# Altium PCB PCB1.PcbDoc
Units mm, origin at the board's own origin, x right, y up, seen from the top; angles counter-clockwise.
Board outline 64.13 x 24.77 mm, 2 copper layers (Top Layer, Bottom Layer); 36 components, 34 nets, 189 pads, 64 vias.
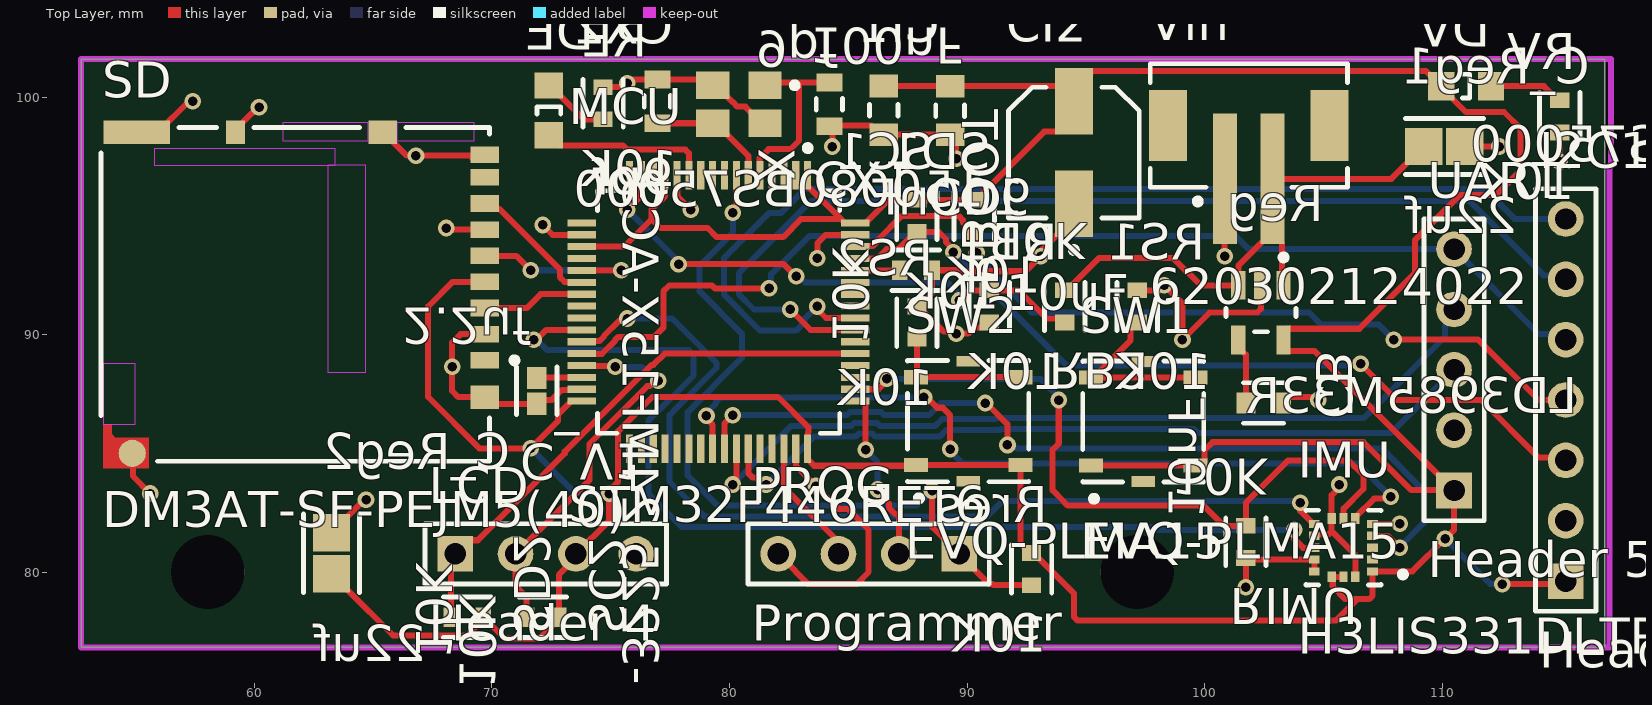
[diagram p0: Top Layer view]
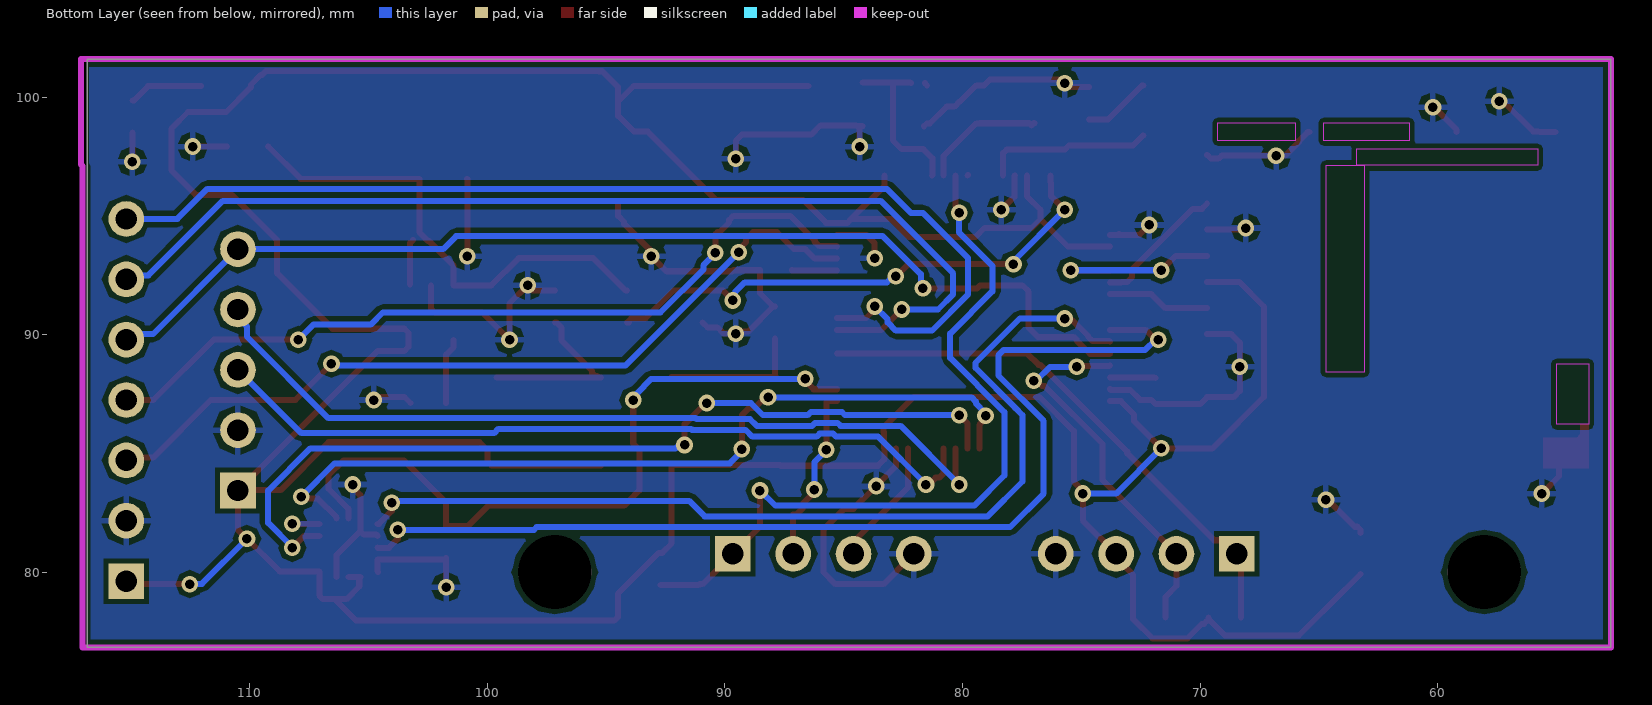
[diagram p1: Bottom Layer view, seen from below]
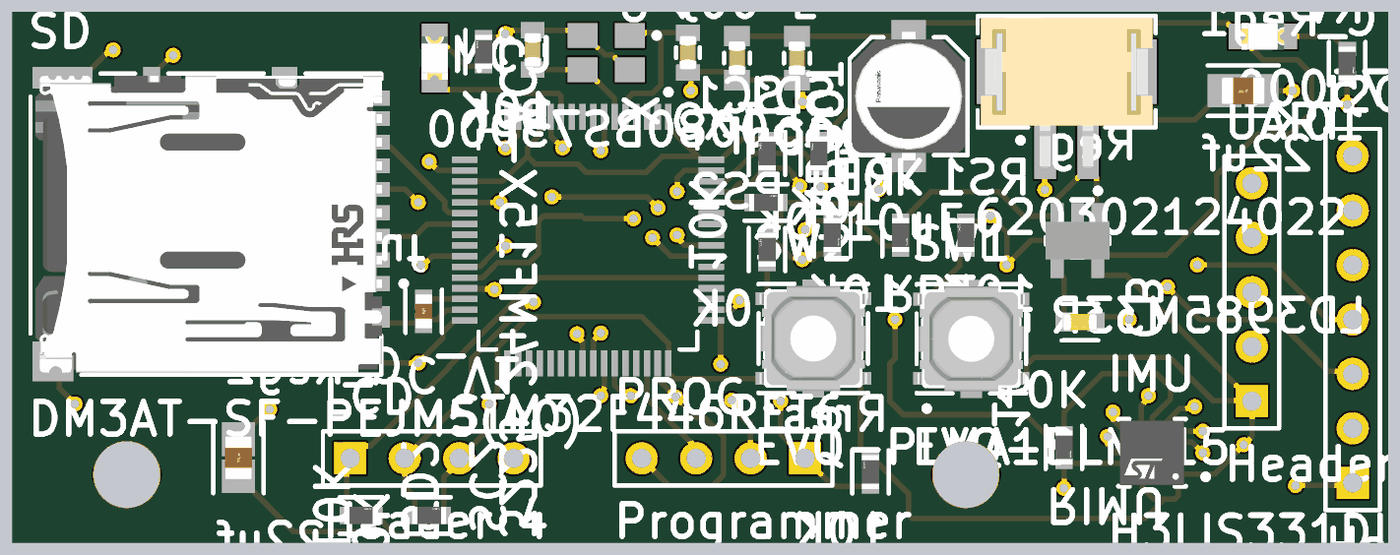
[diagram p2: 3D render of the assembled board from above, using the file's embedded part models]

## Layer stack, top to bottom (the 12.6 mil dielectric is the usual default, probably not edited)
Top Solder: solder mask 0.0102, Solder Resist, Dk 3.5
Top Layer: signal copper 0.0356
Dielectric 1: dielectric 0.32, FR-4, Dk 4.8
Bottom Layer: signal copper 0.0356
Bottom Solder: solder mask 0.0102, Solder Resist, Dk 3.5

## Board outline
52.705,76.835 52.705,101.6 116.84,101.6 116.84,76.835

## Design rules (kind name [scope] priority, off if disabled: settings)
Clearance [All] p1: gap=0.2 ignorepadtopadclearanceinfootprint=FALSE except(0.127: Arc-Arc Arc-Track Track-Track SMDPad-SMDPad)
PolygonConnect [All] p1: connectstyle=Relief reliefconductorwidth=0.254 reliefentries=4 polygonreliefangle="90 Angle" airgapwidth=0.254
RoutingVias [All] p1: holewidth=0.711 width=1.27 viastyle="Through Hole" minholewidth=0.711 minwidth=1.27 maxholewidth=0.711 maxwidth=1.27
SolderMaskExpansion [All] p1: expansion=0.102 istentingtop=FALSE
Width [All] p1: maxlimit=0.5 minlimit=0.254 preferedwidth=0.254
30 further rules are at their usual default settings.

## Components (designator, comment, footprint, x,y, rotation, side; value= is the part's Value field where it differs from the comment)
C_Reg1 "22uf" FP-C2012-125-0_2-IPC_A 110.084,97.917 r180 top
C_Reg2 "22uf" FP-C2012-125-0_2-IPC_A 63.246,80.797 r270 top
C_V1 "2.2uf" FP-C1608-080-0_1-IPC_C 71.882,87.63 r270 top
CB "10nF" FP-CC0603-DA-MFG 102.477,87.122 r0 top value="10 nF"
CD6 "100nF" FP-CGA3E-0_3-0_1-IPC_A 89.281,99.432 r270 top
CI1 "100nF" FP-CGA3E-0_3-0_1-IPC_A 86.487,99.441 r90 top
CI2 "10uF" FP-SC-MFG 94.488,97.663 r90 top
CX1 "9pf" FP-CGA3E-0_3-0_1-IPC_B 84.201,99.695 r270 top
CX2 "9pf" FP-CGA3E-0_3-0_1-IPC_B 76.962,99.822 r90 top
DE "150080BS75000" 0805_A 72.39,99.441 r270 top
DV "150080BS75000" 0805_A 110.998,100.457 r180 top
I2C1 "Header 7" HDR1X7 115.189,79.629 r90 top
IMU "H3LIS331DLTR" FP-TFLGA16-7983231-MFG 105.836,81.034 r180 top
LCD "Header 4" HDR1X4 68.453,80.772 r0 top
MCU "STM32F446RET6" FP-LQFP64-5W-MFG 79.537,90.952 r270 top
PROG "Programmer" HDR1X4 89.662,80.772 r180 top
RB1 "10K" FP-RC0603-0_55-IPC_C 90.932,91.186 r270 top
RB2 "10K" FP-RC0603-0_55-IPC_C 94.107,91.186 r270 top
RBOOT "10K" FP-RC0603-0_55-IPC_C 87.842,92.71 r0 top
RE "10K" FP-RC0603-0_55-IPC_C 74.676,99.737 r90 top
Reg "LD3985M33R" FP-SOT23-5L-7049676-MFG 102.362,90.925 r270 top
RIMU "10K" FP-RC0603-0_55-IPC_C 101.727,81.28 r270 top
Rres "10K" FP-RC0603-0_55-IPC_C 92.71,80.137 r90 top
RS1 "10K" FP-RC0603-0_55-IPC_C 97.155,91.186 r90 top
RS2 "10K" FP-RC0603-0_55-IPC_C 87.884,90.509 r90 top
RV "10K" FP-RC0603-0_55-IPC_C 114.935,99.187 r270 top
SC1 "10K" FP-RC0603-0_55-IPC_C 87.884,94.996 r90 top
SC2 "10K" FP-RC0603-0_55-IPC_C 72.136,78.105 r0 top
SD "DM3AT-SF-PEJM5(40)" FP-DM3AT-SF-PEJM5_40-MFG 61.722,91.694 r270 top
SD1 "10K" FP-RC0603-0_55-IPC_C 90.297,94.996 r90 top
SD2 "10K" FP-RC0603-0_55-IPC_C 68.961,78.105 r0 top
SW1 "EVQ-PLMA15" FP-EVQ-PLMA15-MFG 97.409,86.345 r90 top
SW2 "EVQ-PLMA15" FP-EVQ-PLMA15-MFG 90.043,86.36 r90 top
UART "Header 5" HDR1X5 110.49,83.439 r90 top
Vin "620302124022" 620302124022 101.854,98.806 r180 top
X "TSX-3225 24MF15X-AC3" EPSON-TSX-3225_V 80.391,99.695 r180 top

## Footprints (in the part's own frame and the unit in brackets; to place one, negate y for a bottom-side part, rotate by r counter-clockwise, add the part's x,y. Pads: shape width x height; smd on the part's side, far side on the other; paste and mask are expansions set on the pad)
0805_A [mm] "Chip LED, 2-Leads, Body 2.0x1.3mm, IPC Medium Density"
  rect 1.1x1.2 smd: 1(-1.05,0) 2(1.05,0)
  silkscreen extent -0.15,-0.5 0.15,0.5, body extent -1,-0.63 1,0.63, height 0.68
620302124022 [mm] "2.00mm SMT Male Vertical Shrouded Header, 2p"
  rect 1x5.5 smd: 1(1,2.25) 2(-1,2.25)
  rect 1.6x3 smd: MP1(-3.4,0) MP2(3.4,0)
  silkscreen extent -4.15,-2.6 4.15,3.32, body extent -4,-2.5 4,4.51, height 6.77
EPSON-TSX-3225_V [mm] "SMD, 4-Leads, Body 3.2x2.5mm"
  rect 1.4x1.15 smd: 1(-1.1,-0.8) 2(1.1,-0.8) 3(1.1,0.8) 4(-1.1,0.8)
  silkscreen extent -2.48,-0.92 -2.23,-0.68, body extent -1.6,-1.25 1.6,1.25, height 0.6
FP-C1608-080-0_1-IPC_C [mm]
  rect 0.931x0.812 smd paste+0 mask+0: 1(-0.541,0) 2(0.541,0)
  silkscreen extent -1.01,-0.85 1.01,0.85, body extent -0.8,-0.4 0.8,0.4, height 0.9
FP-C2012-125-0_2-IPC_A [mm]
  rect 1.578x1.556 smd paste+0 mask+0: 1(-0.864,0) 2(0.864,0)
  silkscreen extent -1.65,-1.18 1.65,1.18, body extent -1,-0.63 1,0.63, height 1.45
FP-CC0603-DA-MFG [mm]
  rect 0.8x0.9 smd paste+0 mask+0: 1(-0.75,0) 2(0.75,0)
  silkscreen extent -0.85,-0.85 0.85,0.85, body extent -0.8,-0.4 0.8,0.4, height 0.9
FP-CGA3E-0_3-0_1-IPC_A [mm]
  rect 0.956x1.206 smd paste+0 mask+0: 1(-1.025,0) 2(1.025,0)
  silkscreen extent -0.25,-0.6 0.25,0.6, body extent -0.8,-0.4 0.8,0.4, height 1.1
FP-CGA3E-0_3-0_1-IPC_B [mm]
  rect 0.756x1.106 smd paste+0 mask+0: 1(-0.925,0) 2(0.925,0)
  silkscreen extent -0.25,-0.55 0.25,0.55, body extent -0.8,-0.4 0.8,0.4, height 1.1
FP-DM3AT-SF-PEJM5_40-MFG [mm]
  rect 0.7x1.2 smd paste+0 mask+0: 1(2.775,7.975) 2(1.675,7.975) 3(0.575,7.975) 4(-0.525,7.975) 5(-1.625,7.975) 6(-2.725,7.975) 7(-3.825,7.975) 8(-4.925,7.975) 9(-5.875,7.975)
  rect 1x0.8 smd paste+0 mask+0: 10(-6.825,-2.525)
  rect 1x1.2 smd paste+0 mask+0: 11(4.325,7.975) 12(-6.825,3.675)
  rect 1x2.8 smd paste+0 mask+0: 13(-6.825,-6.675)
  round 1.145 smd paste+0 mask+0: 14(6.689,-6.861)
  Top Layer region: 6.025,-6.175 7.325,-6.175 7.325,-8.075 5.475,-8.075 5.475,-7.725 5.875,-7.725 6.025,-7.575 6.025,-6.175
  Keep-Out Layer region: 2.925,-8.075 5.475,-8.075 5.475,-6.725 2.925,-6.725
  Keep-Out Layer region: -5.425,1.375 3.275,1.375 3.275,2.975 -5.425,2.975
  Keep-Out Layer region: -6.125,-5.925 -5.425,-5.925 -5.425,1.675 -6.125,1.675
  Keep-Out Layer region: -7.225,-0.525 -6.475,-0.525 -6.475,3.075 -7.225,3.075
  Keep-Out Layer region: -7.225,4.275 -6.475,4.275 -6.475,7.525 -7.225,7.525
  silkscreen extent -7.02,-8.17 7.02,9.35, body extent -6.93,-7.95 6.92,8.2, height 1.68
FP-EVQ-PLMA15-MFG [mm]
  rect 0.45x1 smd paste+0 mask+0: 1(-2.525,0) 2(2.525,0)
  rect 0.6x1 smd paste+0 mask+0: A(-1.85,2.2) A'(-1.85,-2.2) B(1.85,2.2) B'(1.85,-2.2)
  silkscreen extent -3.37,-2.55 2.55,2.55, body extent -2.85,-2.8 2.85,2.8, height 0.25
FP-LQFP64-5W-MFG [mm]
  rect 1.2x0.3 smd paste+0 mask+0: 1(-5.75,3.75) 2(-5.75,3.25) 3(-5.75,2.75) 4(-5.75,2.25) 5(-5.75,1.75) 6(-5.75,1.25) 7(-5.75,0.75) 8(-5.75,0.25) 9(-5.75,-0.25) 10(-5.75,-0.75) 11(-5.75,-1.25) 12(-5.75,-1.75) 13(-5.75,-2.25) 14(-5.75,-2.75) 15(-5.75,-3.25) 16(-5.75,-3.75) 33(5.75,-3.75) 34(5.75,-3.25) 35(5.75,-2.75) 36(5.75,-2.25) 37(5.75,-1.75) 38(5.75,-1.25) 39(5.75,-0.75) 40(5.75,-0.25) 41(5.75,0.25) 42(5.75,0.75) 43(5.75,1.25) 44(5.75,1.75) 45(5.75,2.25) 46(5.75,2.75) 47(5.75,3.25) 48(5.75,3.75)
  rect 0.3x1.2 smd paste+0 mask+0: 17(-3.75,-5.75) 18(-3.25,-5.75) 19(-2.75,-5.75) 20(-2.25,-5.75) 21(-1.75,-5.75) 22(-1.25,-5.75) 23(-0.75,-5.75) 24(-0.25,-5.75) 25(0.25,-5.75) 26(0.75,-5.75) 27(1.25,-5.75) 28(1.75,-5.75) 29(2.25,-5.75) 30(2.75,-5.75) 31(3.25,-5.75) 32(3.75,-5.75) 49(3.75,5.75) 50(3.25,5.75) 51(2.75,5.75) 52(2.25,5.75) 53(1.75,5.75) 54(1.25,5.75) 55(0.75,5.75) 56(0.25,5.75) 57(-0.25,5.75) 58(-0.75,5.75) 59(-1.25,5.75) 60(-1.75,5.75) 61(-2.25,5.75) 62(-2.75,5.75) 63(-3.25,5.75) 64(-3.75,5.75)
  silkscreen extent -7.02,-5.1 5.1,5.1
FP-RC0603-0_55-IPC_C [mm]
  rect 0.659x0.812 smd paste+0 mask+0: 1(-0.677,0) 2(0.677,0)
  silkscreen extent -1.01,-0.85 1.01,0.85, body extent -0.8,-0.4 0.8,0.4, height 0.55
FP-SC-MFG [mm]
  rect 2.8x1.6 smd paste+0 mask+0: 1(-2.15,0) 2(2.15,0)
  silkscreen extent -4.22,-2.75 2.75,2.75, body extent -3.8,-3 3.8,3, height 0.25
FP-SOT23-5L-7049676-MFG [mm]
  rect 1.2x0.6 smd paste+0 mask+0: 1(-1.15,0.95) 2(-1.15,0) 3(-1.15,-0.95) 4(1.15,-0.95) 5(1.15,0.95)
  silkscreen extent -2.45,-1.47 0.8,1.47, body extent -0.87,-1.5 0.88,1.5, height 1.45
FP-TFLGA16-7983231-MFG [mm]
  rect 0.45x0.35 smd paste+0 mask+0: 1(-1.225,1) 2(-1.225,0.5) 3(-1.225,0) 4(-1.225,-0.5) 5(-1.225,-1) 9(1.225,-1) 10(1.225,-0.5) 11(1.225,0) 12(1.225,0.5) 13(1.225,1)
  rect 0.35x0.45 smd paste+0 mask+0: 6(-0.5,-1.225) 7(0,-1.225) 8(0.5,-1.225) 14(0.5,1.225) 15(0,1.225) 16(-0.5,1.225)
  silkscreen extent -2.63,-1.57 1.57,1.57, body extent -1.5,-1.5 1.5,1.5, height 1
HDR1X4 [mm] "Connector; Header; 4 Position"
  rect 1.5x1.5 hole 0.9: 1(0,0)
  round 1.5 hole 0.9: 2(2.54,0) 3(5.08,0) 4(7.62,0)
  silkscreen extent -1.27,-1.27 8.89,1.27
HDR1X5 [mm] "Connector; Header; 5 Position"
  rect 1.5x1.5 hole 0.9: 1(0,0)
  round 1.5 hole 0.9: 2(2.54,0) 3(5.08,0) 4(7.62,0) 5(10.16,0)
  silkscreen extent -1.27,-1.27 11.43,1.27
HDR1X7 [mm] "Connector; Header; 7 Position"
  rect 1.5x1.5 hole 0.9: 1(0,0)
  round 1.5 hole 0.9: 2(2.54,0) 3(5.08,0) 4(7.62,0) 5(10.16,0) 6(12.7,0) 7(15.24,0)
  silkscreen extent -1.27,-1.27 16.51,1.27

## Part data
C_Reg1 C_Reg2: library part CMP-08246-007072-1, "Multilayer Ceramic Capacitors 22μF ±20% 16V X6S SMD 0805", Capacitance=22uF, Case Code (Imperial)=0805, Case Code (Metric)=2012, Dielectric=X6S, Dielectric Material=Ceramic, Max Operating Temperature=105°C, Min Operating Temperature=-55°C, Package Quantity=2000, Tolerance=20%, Voltage Rating=16V
C_V1: library part CMP-2000-04981-2, "Multilayer Ceramic Capacitors 4.7μF ±10% 16V X5R SMD 0603", Capacitance=4.7uF, Case Code (Imperial)=0603, Case Code (Metric)=1608, Dielectric=X5R, Dielectric Material=Ceramic, Max Operating Temperature=85°C, Min Operating Temperature=-55°C, Package Quantity=1, Tolerance=10%, Voltage=16V
CB: library part CMP-2100-03600-2, "CAP CER 10000PF 50V X7R 0603", Capacitance="10 nF", Manufacturer=YAGEO, Manufacturer Part Number=CC0603KRX7R9BB103, Package=CC0603-DA, Temperature="-55°C to +125°C", Temperature Characteristic=X7R, Temperature Coefficient=15%, Temperature Range High=+125°C, Temperature Range Low=-55°C, Tolerance=0.1, Voltage="50 V"
CD6 CI1: library part CMP-2000-07546-2, "Cap Ceramic 100nF 50V X7R 10% Pad SMD 0603 +125°C Automotive T/R", Case Code (Imperial)=0603, Case Code (Metric)=1608, Dielectric=X7R, Max Operating Temperature=125°C, Min Operating Temperature=-55°C, Package Quantity=1, Ratings=AEC-Q200, Tolerance=10%, Voltage=50V
CI2: library part CMP-05427-000087-1, "CAP ALUM 10UF 20% 35V SMD", Case/Package=Radial, Leakage Current=3uA, Max Operating Temperature=85°C, Min Operating Temperature=-40°C, Package Quantity=1, Ripple Current=30mA, Tolerance=20%, Voltage=35V
CX1 CX2: library part CMP-08246-000963-1, "Cap Ceramic 9pF 50V C0G 0.5pF Pad SMD 0603 +125°C Automotive T/R", Capacitance=9pF, Case Code (Imperial)=0603, Case Code (Metric)=1608, Dielectric=C0G, Max Operating Temperature=125°C, Min Operating Temperature=-55°C, Package Quantity=4000, Ratings=AEC-Q200, Voltage Rating=50V
DE DV: library part CMP-1426-00008-1, "SMD mono-color Chip LED, WL-SMCW, Blue", Color=Blue, Manufacturer="Wuerth Elektronik"
I2C1: "Header, 7-Pin"
IMU: library part CMP-12175-000002-1, "ACCEL 100-400G I2C/SPI 16TFLGA", Manufacturer=STMicroelectronics, Max Supply Voltage=3.6V, Min Supply Voltage=2.16V, Operating Supply Current=10-300uA, Package=TFLGA16-7983231, Temperature="-40°C to +85°C", Temperature Range High=+85°C, Temperature Range Low=-40°C
LCD: "Header, 4-Pin"
MCU: library part CMP-12105-000007-1, "IC MCU 32BIT 512KB FLASH 64LQFP", Ambient Temperature Range High=+85°C, Ambient Temperature Range Low=-40°C, Frequency=180MHz, Manufacturer=ST, Max Junction Temp=+105°C, Max Supply Voltage=3.6V, Min Supply Voltage=1.7V, Package=LQFP64-5W, Temperature="-40°C to +105°C"
PROG: library part "Header 4", "Header, 4-Pin"
RB1 RB2 RBOOT RE RIMU Rres RS1 RS2 RV SC1 SC2 SD1 SD2: library part CMP-2100-03664-2, "RES 10K OHM 1% 1/10W 0603", Case Code (Imperial)=0603, Case Code (Metric)=1608, Max Operating Temperature=155°C, Max Power Dissipation=100mW, Min Operating Temperature=-55°C, Resistance=10kR, Resistance Tolerance=1%, Resistor Type="Thick Film", Temperature Coefficient=100ppm/°C, Voltage Rating=75V, Voltage Rating (DC)=50V
Reg: library part CMP-0244-00328-2, "IC REG LINEAR 3.3V 150MA SOT23-5", Case/Package=SOT-23, Dropout Voltage=60mV, Input Bias Current=85uA, Max Input Voltage=6V, Max Operating Temperature=125°C, Max Output Current=150mA, Min Current Limit=300mA, Min Input Voltage=2.5V, Min Operating Temperature=-40°C, Min Output Voltage=3.3V, Output Voltage Accuracy=2%, Package Quantity=1, Quiescent Current=150uA
SD: library part CMP-11597-000006-1, "CONN MICRO SD R/A PUSH-PUSH SMD", Color=Black, Contact Resistance=100mR, Current Rating=500mA, Flammability Rating="UL94 V-0", Insulation Resistance=1GR, Max Operating Temperature=85°C, Max Voltage Rating (AC)=125V, Min Operating Temperature=-25°C, Package Quantity=400
SW1 SW2: library part CMP-05618-000006-1, "SWITCH TACTILE SPST-NO 0.02A 15V", Contact Current Rating=20mA, Contact Resistance=50mΩ, Manufacturer="Panasonic Electronic Components", Operating Force=2.6N, Package=0, Temperature="-20°C to +70°C", Temperature Range High=+70°C, Temperature Range Low=-20°C, Voltage Rating Dc=15V
UART: "Header, 5-Pin"
Vin: library part CMP-1502-00660-1, "Male Shrouded Header WR-WTB, SMT, Vertical, pitch 2 mm, 1 x 2 position", Contact Resistance=20mOhm, Manufacturer="Wurth Elektronik", Operating Temperature=-25to85degC, Working Voltage=100VAC
X: library part CMP-2000-07333-1, "MHz Range Crystal, 24 MHz, -40 to 85 degC, 4-Pin SMD, RoHS, Tape and Reel", Frequency=24MHz, Frequency Stability=10PPM, Load Capacitance=9pF, Manufacturer=Epson, Operating Temperature Range=-40Cto+85C, Package / Case=3.2mmx2.5mm, Package Description="4-Pin Surface Mount Device, Body 3.2 x 2.5 mm", Package Reference=TSX-3225

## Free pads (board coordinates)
  oval 3.1x1.524 hole 3.1: 1(58.039,80.01) 1(97.155,80.01)

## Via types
v1: diameter 0.7, hole 0.4, Top Layer to Bottom Layer, 64 vias

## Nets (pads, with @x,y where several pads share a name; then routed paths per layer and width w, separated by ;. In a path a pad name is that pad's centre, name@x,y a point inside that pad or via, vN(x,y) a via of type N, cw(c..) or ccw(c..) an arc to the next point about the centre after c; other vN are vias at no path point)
+3V3: C_Reg2.2 CD6.1 CI1.2 CI2.2 DV.2 I2C1.1 IMU.1 IMU.14 IMU.15 LCD.3 MCU.1 MCU.13 MCU.19 MCU.32 MCU.48 MCU.64 Reg.5 Rres.2 SC1.2 SC2.2 SD1.2 SD2.2 SD.4 SW1.A SW1.A' SW2.A SW2.A' UART.1 | length 195.4
  Top Layer w0.254: C_Reg2.2 63.246,79.922 63.897,79.271 63.908,79.271 65.836,77.343 68.952,77.343 69.638,78.028 SD2.2 ; SD.4 68.343,92.219 67.31,91.186 67.31,87.376 69.469,85.217 v1(71.628,85.217) 72.771,86.36 72.771,86.636 73.337,87.202 MCU.32 ; SD2.2@69.739,77.927 69.84,77.826 69.917,77.826 70.527,77.216 72,77.216 72.813,78.028 SC2.2 72.813,79.893 73.533,80.613 LCD.3 74.93,82.169 74.93,83.433 75.31,83.813 75.31,85.937 76.749,87.376 82.042,87.376 83.312,86.106 83.312,85.896 83.31,85.894 83.31,85.225 MCU.48 83.287,84.752 83.557,84.483 87.658,84.483 87.685,84.51 SW2.A' ; MCU.19 75.555,93.702 76.715,94.862 ; MCU.13 77.287,95.829 76.715,95.257 76.715,94.862 ; MCU.1 83.287,96.252 84.67,94.869 ; CI1.2 89.272,100.466 CD6.1 93.844,100.457 CI2.2 ; SW2.A'@92.243,84.502 92.243,81.204 92.633,80.814 Rres.2 92.787,80.814 94.488,79.112 94.488,78.127 94.637,77.978 105.526,77.978 106.415,78.867 ; SW1.A SW1.A' ; SW1.A'@99.624,84.495 99.809,84.495 99.982,84.668 99.982,85.123 100.33,85.471 106.68,85.471 108.694,83.457 110.472,83.457 104.619,89.31 103.485,89.31 103.312,89.483 Reg.5 103.312,90.075 103.485,90.248 106.504,90.248 108.839,92.583 108.839,93.98 110.744,95.885 112.268,95.885 113.284,96.901 113.284,98.679 112.592,99.371 110.984,99.371 109.948,100.407 109.948,100.507 109.525,100.93 109.475,100.93 109.313,101.092 95.31,101.092 95.304,101.086 95.161,101.086 94.488,100.413 CI2.2 ; IMU.15 IMU.14 105.384,79.761 105.384,79.401 105.918,78.867 106.415,78.867 ; UART.1 110.49,81.788 v1(110.109,81.407) 108.736,80.034 IMU.1 107.061,79.016 106.912,78.867 106.415,78.867 ; v1(112.522,79.502) 115.062,79.502 I2C1.1 ; 76.715,94.862 77.089,94.488 79.08,94.488 79.461,94.107 82.251,94.107 83.013,94.869 84.67,94.869 ; 84.67,94.869 MCU.64@84.837,94.702 ; 84.67,94.869 MCU.64@84.837,94.702 ; MCU.64@84.837,94.702 MCU.64 ; MCU.64@84.837,94.702 MCU.64 ; MCU.64 85.737,94.702 86.708,95.673 SC1.2 SD1.2 90.374,95.673 93.241,98.54 93.815,98.54 94.488,99.213 CI2.2
  Bottom Layer w0.254: v1(71.628,85.217) 73.533,83.312 v1(74.93,83.312) ; v1(110.109,81.407) 112.005,79.511 112.513,79.511 v1(112.522,79.502)
ADC0: MCU.15 RB1.1 RB2.2 | length 22.7
  Top Layer w0.254: v1(75.692,95.25) 76.264,95.822 76.264,96.393 76.287,96.416 MCU.15 ; v1(77.851,92.964) 82.278,92.964 82.786,92.456 v1(82.804,92.456) ; v1(89.662,91.44) 90.085,91.863 RB1.1 92.16,91.863 93.345,90.678 93.938,90.678 RB2.2 RB2.2@94.03,90.509
  Bottom Layer w0.254: v1(75.692,95.25) v1@77.915,93.027 ; v1(82.804,92.456) 82.922,92.456 83.176,92.202 89.154,92.202 89.577,91.779 89.577,91.525 v1(89.662,91.44)
GND: C_Reg1.1 C_Reg2.1 C_V1.2 CB.2 CD6.2 CI1.1 CI2.1 CX1.2 CX2.2 I2C1.2 IMU.5 IMU.8 IMU.10 IMU.12 IMU.13 IMU.16 LCD.4 MCU.12 MCU.18 MCU.31 MCU.47 MCU.63 PROG.4 RB1.2 RBOOT.2 RE.2 Reg.2 RIMU.2 RS1.2 RS2.2 RV.2 SD.2 SD.6 SD.9 SD.10 SD.11 SD.12 SD.13 SD.14 UART.2 Vin.1 X.2 X.4 | length 98
  Top Layer w0.254: SD.14 54.886,84.98 54.886,84.052 v1(55.626,83.312) ; SD.13 55.72,98.519 55.753,98.552 55.98,98.552 57.25,99.822 v1(57.404,99.822) ; SD.10 59.197,98.619 60.146,99.568 v1(60.198,99.568) ; C_Reg2.1 63.246,81.788 63.373,81.915 63.489,81.915 64.632,83.058 v1(64.701,83.058) v1@64.77,83.058 ; SD.12 65.472,98.519 65.845,98.146 65.845,98.106 66.414,97.536 v1(66.802,97.536) 69.088,97.536 69.215,97.409 69.537,97.409 SD.9 ; v1(68.072,94.488) 68.141,94.419 SD.6 ; SD.2 68.683,90.019 68.326,89.662 v1(68.326,88.646) 68.326,87.63 68.587,87.369 SD.11 69.976,87.089 C_V1.2 72.045,87.252 72.52,87.252 72.947,87.679 73.764,87.679 MCU.31 ; v1(72.136,94.615) 72.549,94.202 73.383,94.202 73.406,94.225 73.429,94.202 MCU.18 ; RE.2 75.521,100.413 v1(75.688,100.58) 75.855,100.747 CX2.2 78.831,100.747 79.083,100.495 X.2 79.416,100.495 80.114,99.797 80.126,99.797 80.33,99.593 80.668,99.593 81.366,98.895 X.4 X.4@81.616,98.77 ; MCU.12 77.81,96.679 77.81,95.799 v1(78.359,95.25) ; PROG.4@81.804,80.196 82.252,80.645 82.296,80.645 82.169,80.772 PROG.4 82.211,80.603 83.312,79.502 85.344,79.502 85.852,80.01 85.852,81.788 84.974,82.666 84.593,82.666 v1(83.629,83.629) 82.804,84.455 82.804,85.185 MCU.47 ; v1(83.693,93.218) 83.693,93.851 84.044,94.202 MCU.63 ; CX1.2 CX1.2@84.31,98.77 ; v1(84.328,97.917) 84.328,98.752 CX1.2@84.31,98.77 ; RS2.2 RS2.2@87.961,91.186 ; v1(89.535,97.409) 89.535,98.153 CD6.2 89.272,98.416 CI1.1 86.362,98.416 85.972,98.806 84.455,98.806 84.419,98.77 CX1.2@84.31,98.77 ; RB1.2 90.73,90.307 90.307,90.307 90.043,90.043 v1(89.535,90.043) 89.45,90.128 89.018,90.128 RS2.2@87.961,91.186 ; v1(93.091,93.303) 92.456,92.668 89.672,92.668 89.629,92.71 RBOOT.2 88.519,91.744 RS2.2@87.961,91.186 ; v1@93.176,93.601 94.234,94.659 94.234,94.742 94.488,94.996 CI2.1 ; RS1.2 98.086,91.863 v1(98.298,92.075) 99.06,91.313 v1(99.06,89.789) 100.203,90.932 102.213,90.932 102.362,91.081 Reg.2 ; v1(100.838,93.303) 100.838,96.54 Vin.1 ; v1(101.727,79.375) RIMU.2 101.796,80.534 IMU.12 IMU.13 IMU.13@104.587,80.01 ; CB.2 103.481,87.376 104.648,87.376 v1(104.775,87.249) ; IMU.10 104.659,81.582 105.187,81.582 105.336,81.731 ; v1(105.664,83.693) 105.664,83.572 105.336,83.244 IMU.8 105.336,81.731 ; IMU.16 106.336,80.731 105.336,81.731 ; IMU.5 108.196,82.034 v1(108.2,82.038) v1@108.204,82.042 ; C_Reg1.1 v1(112.395,97.917) ; v1(114.935,97.282) RV.2
INDICATOR: DE.2 MCU.11 | length 7.1
  Top Layer w0.254: DE.2 72.813,97.968 75.514,97.968 75.692,97.79 78.138,97.79 78.287,97.641 MCU.11
"INT 1": IMU.11 MCU.26 | length 45
  Top Layer w0.254: v1(71.755,89.789) 71.876,89.789 72.289,90.202 MCU.26 ; v1(103.759,81.788) 103.759,81.407 104.14,81.026 104.603,81.026 IMU.11
  Bottom Layer w0.254: v1(71.755,89.789) 71.876,89.789 72.32,89.344 78.274,89.344 78.486,89.132 78.486,88.279 76.581,86.374 76.581,83.312 77.997,81.896 97.923,81.896 98.031,81.788 v1(103.759,81.788)
"INT 2": IMU.9 MCU.27 | length 41.3
  Top Layer w0.254: MCU.27 73.81,89.725 74.522,89.725 74.714,89.917 74.714,89.949 75.358,90.593 75.607,90.593 v1(75.692,90.678) ; v1(104.013,82.931) 104.013,82.582 104.561,82.034 IMU.9
  Bottom Layer w0.254: v1(75.692,90.678) 77.583,90.678 79.45,88.811 79.45,88.601 77.778,86.929 77.778,86.922 77.47,86.614 77.47,83.82 78.94,82.35 90.846,82.35 91.5,83.004 103.94,83.004 v1(104.013,82.931)
"INT 3": I2C1.5 MCU.28 UART.5 | length 46.6
  Top Layer w0.254: MCU.28 73.802,89.187 74.627,89.187 75.168,89.729 75.168,89.761 75.317,89.909 76.828,89.909 77.216,90.297 77.216,91.821 77.47,92.075 79.254,92.075 79.381,91.948 v1(81.661,91.948)
  Bottom Layer w0.254: v1(81.661,91.948) 81.746,92.033 81.746,92.541 83.354,94.149 101.304,94.149 101.854,93.599 UART.5 114.062,90.027 114.951,90.027 I2C1.5
"INT 4": I2C1.6 MCU.55 | length 43.8
  Top Layer w0.254: v1(82.55,91.059) 83.407,90.202 MCU.55
  Bottom Layer w0.254: v1(82.55,91.059) 81.026,91.059 80.391,91.694 80.391,92.583 83.439,95.631 111.125,95.631 114.262,92.494 115.024,92.494 I2C1.6
"INT 5": I2C1.7 MCU.56 | length 45.6
  Top Layer w0.254: v1(83.693,91.186) 83.693,91.065 84.056,90.702 MCU.56
  Bottom Layer w0.254: v1(83.693,91.186) 83.15,90.643 83.15,90.516 82.804,90.17 81.28,90.17 79.756,91.694 79.756,93.218 81.661,95.123 82.169,95.123 83.185,96.139 111.774,96.139 113.044,94.869 I2C1.7
M_boot: MCU.60 RBOOT.1 | length 1.9
  Top Layer w0.254: MCU.60 87.158,92.702 RBOOT.1
M_C_V: C_V1.1 MCU.30 | length 1.9
  Top Layer w0.254: C_V1.1 71.913,88.202 MCU.30
M_X1: CX1.1 MCU.5 X.1 | length 7.3
  Top Layer w0.254: MCU.5 81.264,96.725 81.264,97.425 81.644,97.805 82.565,97.805 82.931,98.171 82.931,100.62 ; X.1 X.1@81.58,100.584 ; X.1@82.169,100.584 82.205,100.62 82.931,100.62 ; CX1.1 82.931,100.62
M_X2: CX2.1 MCU.6 X.3 | length 5.3
  Top Layer w0.254: CX2.1 76.998,98.897 77.089,98.806 77.18,98.897 79.289,98.897 X.3 79.416,98.895 80.787,97.524 MCU.6
MISO: MCU.22 SD.7 | length 5.7
  Top Layer w0.254: SD.7 69.92,95.296 70.312,95.296 72.86,92.748 72.86,92.417 73.052,92.225 73.314,92.225 73.337,92.202 MCU.22
MOSI: MCU.23 SD.3 | length 4.3
  Top Layer w0.254: SD.3 71.462,91.119 72.045,91.702 MCU.23
NetCB_1: CB.1 Reg.4 | length 2.8
  Top Layer w0.254: Reg.4 101.412,89.475 101.727,89.16 CB.1
NetDE_1: DE.1 RE.1 | length 2.9
  Top Layer w0.254: DE.1 72.44,100.491 73.871,99.06 RE.1
NetDV_1: DV.1 RV.1 | length 3.1
  Top Layer w0.254: DV.1 114.265,100.457 114.858,99.864 RV.1
NRST: MCU.7 PROG.1 Rres.1 | length 32.8
  Top Layer w0.254: v1(80.137,95.123) 80.137,95.244 80.287,95.394 MCU.7 ; v1(88.519,83.439) 88.519,81.915 PROG.1 90.932,79.502 91.059,79.502 91.101,79.46 Rres.1
  Bottom Layer w0.254: v1(80.137,95.123) 80.137,94.293 78.74,92.896 78.74,91.821 80.518,90.043 80.518,89.027 78.232,86.741 78.232,84.074 79.502,82.804 87.866,82.804 88.501,83.439 v1(88.519,83.439)
RX: MCU.43 UART.3 | length 33.2
  Top Layer w0.254: MCU.43 80.787,84.159 80.967,83.98 81.127,83.98 81.413,83.693 v1(81.534,83.693)
  Bottom Layer w0.254: v1(81.534,83.693) 83.547,85.706 85.314,85.706 85.445,85.837 86.005,85.837 86.136,85.706 88.843,85.706 89.128,85.991 91.37,85.991 91.414,86.035 99.527,86.035 99.71,85.852 107.823,85.852 UART.3
S1: RS1.1 SW1.B SW1.B' | length 7.6
  Top Layer w0.254: SW1.B SW1.B@95.307,88.195 ; RS1.1 97.078,90.509 96.876,90.307 96.876,89.764 95.582,88.47 95.582,88.368 95.479,88.265 95.377,88.265 SW1.B@95.307,88.195 ; SW1.B' SW1.B@95.307,88.195
S2: RS2.1 SW2.B SW2.B' | length 6
  Top Layer w0.254: RS2.1 87.884,88.251 SW2.B SW2.B'
SA_IMU: IMU.7 MCU.50 RIMU.1 | length 31
  Top Layer w0.254: MCU.50 86.259,87.702 86.614,88.057 v1(86.614,88.138) ; v1(93.853,87.249) 93.853,85.414 93.599,85.16 93.599,83.445 94.044,83.001 94.044,82.994 94.234,82.804 99.949,82.804 100.796,81.957 RIMU.1 101.727,82.931 103.505,84.709 106.045,84.709 106.68,84.074 106.68,83.513 105.846,82.68 105.846,82.269 IMU.7
  Bottom Layer w0.254: v1(86.614,88.138) 93.097,88.138 93.408,87.827 93.408,87.814 93.853,87.37 v1(93.853,87.249)
SCK: MCU.21 SD.5 | length 7.6
  Top Layer w0.254: SD.5 71.019,93.319 v1(71.628,92.71) ; MCU.21 73.791,92.706 75.434,92.706 v1(75.438,92.71)
  Bottom Layer w0.254: v1(71.628,92.71) v1(75.438,92.71)
SCL1: I2C1.3 MCU.61 SC1.1 | length 34.6
  Top Layer w0.254: MCU.61 86.217,93.202 86.614,93.599 87.087,93.599 87.807,94.319 SC1.1 88.815,94.319 89.108,94.026 89.108,93.893 89.408,93.593 v1(89.408,93.472) ; v1(106.553,88.773) 108.077,87.249 111.633,87.249 114.058,84.824 115.074,84.824 I2C1.3
  Bottom Layer w0.254: v1(89.408,93.472) 94.186,88.694 106.474,88.694 v1(106.553,88.773)
SCL2: LCD.2 MCU.29 SC2.1 | length 16.3
  Top Layer w0.254: SC2.1 71.459,78.956 70.993,79.422 LCD.2 74.097,83.876 74.097,85.4 76.527,87.83 76.653,87.83 76.876,88.053 v1(76.996,88.053) ; MCU.29 73.81,88.679 75.151,88.679 v1(75.184,88.646)
  Bottom Layer w0.254: v1(75.184,88.646) 76.309,88.646 76.902,88.053 v1(76.996,88.053)
SCL3: IMU.4 MCU.41 | length 37.2
  Top Layer w0.254: MCU.41 79.787,86.264 v1(80.137,86.614) ; v1(90.763,87.122) 90.805,87.122 91.694,86.233 v1(91.694,85.358) ; IMU.4 107.696,81.534 v1(108.204,81.026)
  Bottom Layer w0.254: v1(80.137,86.614) 84.938,86.614 85.068,86.745 86.382,86.745 86.512,86.614 88.392,86.614 88.9,87.122 v1(90.763,87.122) ; v1(91.694,85.358) 91.779,85.272 92.01,85.272 92.066,85.217 107.442,85.217 109.22,83.439 109.22,82.079 108.204,81.063 v1(108.204,81.026)
SDA1: I2C1.4 MCU.62 SD1.1 | length 34.3
  Top Layer w0.254: MCU.62 85.31,93.725 86.022,93.725 86.214,93.917 86.214,93.961 87.249,94.996 89.64,94.996 89.82,94.816 89.82,94.72 90.22,94.319 SD1.1 90.396,94.22 v1(90.396,93.442) ; v1(107.95,89.789) 111.506,89.789 114.046,87.249 I2C1.4
  Bottom Layer w0.254: v1(90.396,93.442) 90.396,93.426 90.905,92.917 90.905,92.737 92.71,90.932 104.394,90.932 104.902,90.424 107.315,90.424 v1(107.95,89.789)
SDA2: LCD.1 MCU.53 SD2.1 | length 23.2
  Top Layer w0.254: SD2.1 68.284,80.306 68.199,80.391 68.453,80.645 LCD.1 69.028,81.347 69.409,81.347 73.062,85 73.062,85.077 76.716,88.73 76.792,88.73 77.264,89.202 MCU.53
SDA3: IMU.6 MCU.40 | length 35.2
  Top Layer w0.254: v1(79.028,86.58) 79.028,86.459 79.287,86.2 MCU.40 ; v1(88.181,87.36) 88.301,87.36 88.738,86.923 88.972,86.923 89.281,86.614 v1(89.281,85.187) ; IMU.6 106.336,82.309 107.127,83.1 107.738,83.1 v1(107.823,83.185)
  Bottom Layer w0.254: v1(79.028,86.58) 79.028,86.7 79.433,87.106 79.433,87.18 79.613,87.36 v1(88.181,87.36) ; v1(89.281,85.187) 89.281,85.09 89.789,84.582 106.426,84.582 v1(107.823,83.185)
SWCLK: MCU.49 PROG.2 | length 7.5
  Top Layer w0.254: MCU.49 85.702,87.202 85.725,87.179 v1(85.725,85.16) ; v1(86.233,83.481) 86.233,83.365 86.7,82.898 86.7,82.718 86.995,82.423 87.122,82.423 PROG.2
  Bottom Layer w0.254: v1(85.725,85.16) 85.725,85.142 86.233,84.634 v1(86.233,83.481)
SWDIO: MCU.46 PROG.3 | length 5.2
  Top Layer w0.254: MCU.46 82.287,83.575 PROG.3@84.814,81.048
TX: MCU.42 UART.4 | length 35.5
  Top Layer w0.254: v1(80.137,83.693) 80.137,83.814 80.287,83.964 MCU.42
  Bottom Layer w0.254: v1(80.137,83.693) 82.604,86.16 85.126,86.16 85.257,86.291 86.193,86.291 86.324,86.16 88.655,86.16 88.94,86.445 91.182,86.445 91.226,86.489 106.682,86.489 110.109,89.916 110.109,90.341 110.49,90.722 UART.4
Vin: C_Reg1.2 RB2.1 Reg.1 Reg.3 Vin.2 | length 22.3
  Top Layer w0.254: RB2.1 94.184,91.863 95.539,93.218 98.679,93.218 99.822,92.075 Reg.3 101.416,92.079 101.416,92.907 102.442,93.933 102.481,93.933 102.854,94.306 Vin.2 107.848,96.556 109.209,97.917 C_Reg1.2 ; Vin.2@103.124,93.98 103.251,93.853 Reg.1@103.251,92.119
pads on no net: IMU.2 IMU.3 MCU.2 MCU.3 MCU.4 MCU.8 MCU.9 MCU.10 MCU.14 MCU.16 MCU.17 MCU.20 MCU.24 MCU.25 MCU.33 MCU.34 MCU.35 MCU.36 MCU.37 MCU.38 MCU.39 MCU.44 MCU.45 MCU.51 MCU.52 MCU.54 MCU.57 MCU.58 MCU.59 SD.1 SD.8 SW1.1 SW1.2 SW2.1 SW2.2 Vin.MP1 Vin.MP2
copper on no net: | length 0
  Top Layer w0.254: 79.764,96.725 79.787,96.702

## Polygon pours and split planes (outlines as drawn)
GND on Bottom Layer "GND_L02_P000" (solid, remove dead copper, pour order 0): 51.101,103.112 51.228,103.239 118.157,103.239 118.157,74.918 50.384,74.918

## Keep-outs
Keep-Out Layer:
  lines w0.254: 52.705,76.835 52.705,101.6 117.094,101.6 117.094,97.155 117.031,97.092 117.031,76.835 109.093,76.835 52.705,76.835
